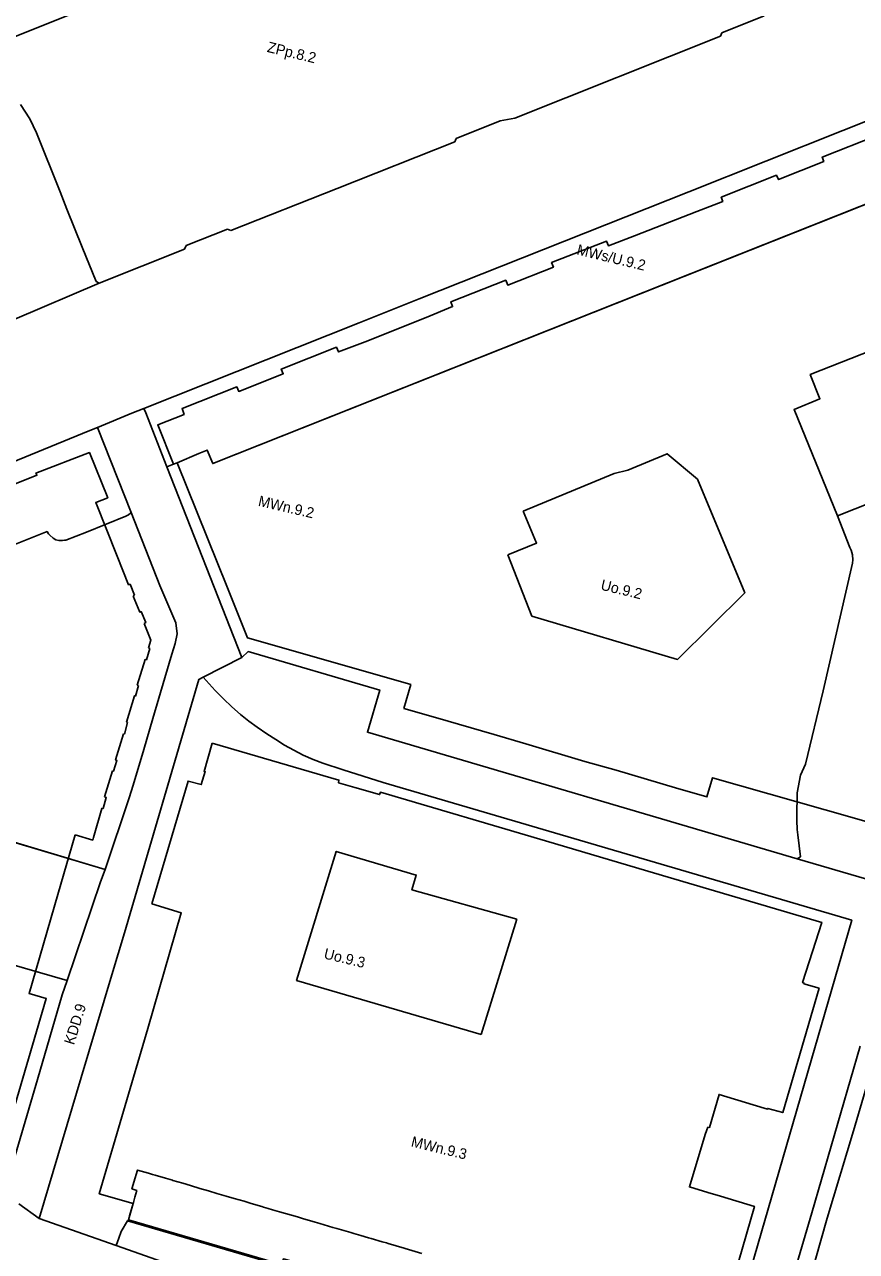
# Model space of a CAD drawing. Extents: x 7429686 to 7432896, y 5547954 to 5550600.
# Drawn here: x 7431433.9 to 7431748.3, y 5548706.1 to 5549169.6 of the extents above; entities that cross this region are included whole.
import ezdxf

# ---------------------------------------------------------------- set-up
doc = ezdxf.new("R2010")
doc.units = 0
for name, color, linetype in [('linie rozgraniczające', 7, 'Continuous'), ('obowiązująca linia zabudowy', 7, 'Continuous'), ('oznaczenia przeznaczeń', 7, 'Continuous')]:
    doc.layers.add(name, color=color, linetype=linetype)

msp = doc.modelspace()

# ---------------------------------------------------------------- linework, layer by layer
at = {"layer": 'linie rozgraniczające'}
for p, q in [((7431785.66, 5549115.2), (7431504.99, 5549003.74)), ((7431724.7, 5549024.21), (7431734.44, 5549028.21)), ((7431741.14, 5548983.95), (7431724.7, 5549024.21)), ((7431502.92, 5549008.85), (7431499.75, 5549007.52)), ((7431504.99, 5549003.74), (7431502.92, 5549008.85)), ((7431487.65, 5549002.56), (7431515.97, 5548930.47)), ((7431474.14, 5548985.19), (7431473.9, 5548984.95)), ((7431627.4, 5548973.7), (7431622.25, 5548985.72)), ((7431616.56, 5548969.31), (7431627.4, 5548973.7)), ((7431489.56, 5548931.69), (7431490.75, 5548935.82)), ((7431486.92, 5548922.77), (7431489.56, 5548931.69)), ((7431515.97, 5548930.47), (7431518.44, 5548932.69)), ((7431482.34, 5548907.49), (7431486.92, 5548922.77)), ((7431503.63, 5548920.58), (7431501.41, 5548923.1)), ((7431512.23, 5548911.8), (7431509.04, 5548914.81)), ((7431478.91, 5548895.76), (7431482.34, 5548907.49)), ((7431528.82, 5548899.44), (7431525.48, 5548901.64)), ((7431532.17, 5548897.4), (7431528.82, 5548899.44)), ((7431474.89, 5548882.25), (7431478.91, 5548895.76)), ((7431473.46, 5548877.47), (7431474.89, 5548882.25)), ((7431725.8, 5548877.54), (7431725.87, 5548879.36)), ((7431464.36, 5548850.33), (7431473.46, 5548877.47)), ((7431411.82, 5548866.07), (7431464.36, 5548850.33)), ((7431725.87, 5548854.38), (7431727.1, 5548855.2)), ((7431606.38, 5548788.03), (7431619.85, 5548831.65)), ((7431619.85, 5548831.65), (7431606.38, 5548788.03)), ((7431449.93, 5548808.45), (7431398.8, 5548823.21)), ((7431448.1, 5548803.02), (7431449.93, 5548808.45)), ((7431475.17, 5548732.25), (7431476.53, 5548736.85)), ((7431476.53, 5548736.85), (7431480.69, 5548735.63)), ((7431474.54, 5548730.08), (7431475.17, 5548732.25)), ((7431480.69, 5548735.63), (7431482.22, 5548735.18)), ((7431487.16, 5548733.74), (7431489.74, 5548732.98)), ((7431489.74, 5548732.98), (7431489.9, 5548732.93)), ((7431489.9, 5548732.93), (7431493.63, 5548731.84)), ((7431493.63, 5548731.84), (7431496.63, 5548730.96)), ((7431474.46, 5548729.81), (7431474.54, 5548730.08)), ((7431476.26, 5548729.09), (7431474.46, 5548729.81)), ((7431475.06, 5548724.64), (7431475.6, 5548726.65)), ((7431475.6, 5548726.65), (7431476.26, 5548729.09)), ((7431496.63, 5548730.96), (7431500.1, 5548729.94)), ((7431500.1, 5548729.94), (7431503.35, 5548728.99)), ((7431510.07, 5548727.02), (7431513.04, 5548726.15)), ((7431473.53, 5548719.51), (7431474.94, 5548724.18)), ((7431474.94, 5548724.18), (7431475.06, 5548724.64)), ((7431513.04, 5548726.15), (7431516.81, 5548725.05)), ((7431516.81, 5548725.05), (7431519.52, 5548724.26)), ((7431519.52, 5548724.26), (7431523.52, 5548723.08)), ((7431523.52, 5548723.08), (7431524.18, 5548722.89)), ((7431524.18, 5548722.89), (7431525.99, 5548722.36)), ((7431525.99, 5548722.36), (7431527.63, 5548721.88)), ((7431527.63, 5548721.88), (7431530.25, 5548721.12)), ((7431439.45, 5548718.51), (7431468.45, 5548708.34)), ((7431470.33, 5548713.59), (7431472.83, 5548717.66)), ((7431472.83, 5548717.66), (7431473.1, 5548718.1)), ((7431473.1, 5548718.1), (7431473.53, 5548719.51)), ((7431530.25, 5548721.12), (7431532.46, 5548720.47)), ((7431537.79, 5548718.9), (7431538.93, 5548718.57)), ((7431538.93, 5548718.57), (7431543.7, 5548717.17)), ((7431543.7, 5548717.17), (7431545.4, 5548716.68)), ((7431551.87, 5548714.78), (7431557.15, 5548713.23)), ((7431561.01, 5548712.1), (7431563.87, 5548711.27)), ((7431563.87, 5548711.27), (7431564.82, 5548710.99)), ((7431564.82, 5548710.99), (7431569.03, 5548709.75)), ((7431569.03, 5548709.75), (7431570.6, 5548709.3)), ((7431570.6, 5548709.3), (7431571.29, 5548709.09)), ((7431571.29, 5548709.09), (7431577.32, 5548707.33)), ((7431577.32, 5548707.33), (7431577.76, 5548707.2)), ((7431577.76, 5548707.2), (7431584.04, 5548705.36))]:
    msp.add_line(p, q, dxfattribs=at)
for points in [[(7431418.23, 5549160.27), (7431452.13, 5549173.77)], [(7431713.37, 5549172.84), (7431697.41, 5549166.43)], [(7431696.87, 5549165.14), (7431619.13, 5549134.23)], [(7431697.41, 5549166.43), (7431696.87, 5549165.14)], [(7431435.89, 5549133.99), (7431432.34, 5549139.33)], [(7431684.85, 5549106.33), (7431772.2, 5549141.08)], [(7431438.37, 5549128.66), (7431435.89, 5549133.99)], [(7431613.58, 5549133.25), (7431597.01, 5549126.59)], [(7431619.13, 5549134.23), (7431613.58, 5549133.25)], [(7431447.31, 5549106.39), (7431438.37, 5549128.66)], [(7431596.48, 5549125.24), (7431552, 5549107.62)], [(7431597.01, 5549126.59), (7431596.48, 5549125.24)], [(7431487.65, 5549002.56), (7431490.16, 5549003.53), (7431491.56, 5549004.06), (7431499.75, 5549007.52), (7431502.92, 5549008.85), (7431504.99, 5549003.74), (7431785.66, 5549115.2)], [(7431552, 5549107.62), (7431511.87, 5549091.76)], [(7431449.91, 5549099.9), (7431447.31, 5549106.39)], [(7431582.95, 5549065.95), (7431684.85, 5549106.33)], [(7431455.71, 5549085.44), (7431449.91, 5549099.9)], [(7431510.54, 5549092.31), (7431494.96, 5549086.12)], [(7431511.87, 5549091.76), (7431510.54, 5549092.31)], [(7431460.92, 5549072.46), (7431455.71, 5549085.44)], [(7431494.37, 5549084.78), (7431462.06, 5549071.92)], [(7431494.96, 5549086.12), (7431494.37, 5549084.78)], [(7431430.25, 5549058.28), (7431462.06, 5549071.92)], [(7431462.06, 5549071.92), (7431460.92, 5549072.46)], [(7431560.27, 5549056.88), (7431582.95, 5549065.95)], [(7431479.01, 5549024.58), (7431560.27, 5549056.88)], [(7431798.27, 5549018.65), (7431791.38, 5549035.58), (7431789.74, 5549039.66), (7431778.26, 5549035.05), (7431777.18, 5549034.62), (7431769.87, 5549052.73), (7431730.81, 5549037.32), (7431734.44, 5549028.21), (7431724.7, 5549024.21), (7431741.14, 5548983.95)], [(7431734.44, 5549028.21), (7431730.81, 5549037.32), (7431769.87, 5549052.73), (7431777.18, 5549034.62), (7431778.26, 5549035.05)], [(7431474.47, 5549022.72), (7431479.01, 5549024.58)], [(7431479.65, 5549022.93), (7431479.01, 5549024.58)], [(7431461.42, 5549017.39), (7431474.47, 5549022.72)], [(7431487.65, 5549002.56), (7431479.65, 5549022.93)], [(7431458.52, 5549016.21), (7431381.36, 5548984.68)], [(7431461.42, 5549017.39), (7431458.52, 5549016.21)], [(7431474.14, 5548985.19), (7431461.42, 5549017.39)], [(7431499.75, 5549007.52), (7431491.56, 5549004.06), (7431490.16, 5549003.53), (7431487.65, 5549002.56)], [(7431616.56, 5548969.31), (7431625.6, 5548946.1), (7431680.64, 5548929.72), (7431706.02, 5548954.88), (7431688.21, 5548997.84), (7431676.68, 5549007.45), (7431661.81, 5549001.29), (7431656.64, 5548999.97), (7431622.25, 5548985.72)], [(7431622.25, 5548985.72), (7431656.64, 5548999.97), (7431661.81, 5549001.29), (7431676.68, 5549007.45), (7431688.21, 5548997.84)], [(7431741.14, 5548983.95), (7431802.38, 5549008.24)], [(7431515.97, 5548930.47), (7431487.65, 5549002.56)], [(7431688.21, 5548997.84), (7431706.02, 5548954.88), (7431680.64, 5548929.72), (7431625.6, 5548946.1), (7431616.56, 5548969.31)], [(7431425.44, 5548971.3), (7431442.42, 5548978.05), (7431442.93, 5548977.2), (7431443.45, 5548976.63), (7431444.69, 5548975.54), (7431445.74, 5548974.96), (7431446.79, 5548974.7), (7431447.58, 5548974.62), (7431448.24, 5548974.62), (7431449.01, 5548974.74), (7431449.47, 5548974.86), (7431457.29, 5548977.87), (7431472.2, 5548983.89), (7431473.17, 5548984.4), (7431473.9, 5548984.95), (7431474.14, 5548985.19)], [(7431473.9, 5548984.95), (7431473.17, 5548984.4), (7431472.2, 5548983.89), (7431457.29, 5548977.87), (7431449.47, 5548974.86), (7431449.01, 5548974.74), (7431448.24, 5548974.62), (7431447.58, 5548974.62), (7431446.79, 5548974.7), (7431445.74, 5548974.96), (7431444.69, 5548975.54), (7431443.45, 5548976.63), (7431442.93, 5548977.2), (7431442.42, 5548978.05)], [(7431474.14, 5548985.19), (7431485.04, 5548957.62), (7431491, 5548943.55), (7431491.6, 5548939.41), (7431490.75, 5548935.82), (7431489.56, 5548931.69), (7431486.92, 5548922.77), (7431482.34, 5548907.49), (7431478.91, 5548895.76), (7431474.89, 5548882.25), (7431473.46, 5548877.47), (7431464.36, 5548850.33)], [(7431491, 5548943.55), (7431485.04, 5548957.62), (7431474.14, 5548985.19)], [(7431622.25, 5548985.72), (7431627.4, 5548973.7), (7431616.56, 5548969.31)], [(7431741.14, 5548983.95), (7431745.78, 5548971.99), (7431746.27, 5548971.03), (7431746.77, 5548969.28), (7431746.85, 5548967.38), (7431746.71, 5548966.07), (7431735.66, 5548917.92), (7431729, 5548890.15), (7431727.13, 5548886.07), (7431725.87, 5548879.36), (7431725.8, 5548877.54), (7431725.78, 5548872.17), (7431725.77, 5548868.88), (7431725.89, 5548865.49), (7431726.11, 5548863.45), (7431727.1, 5548855.2), (7431725.87, 5548854.38)], [(7431729, 5548890.15), (7431735.66, 5548917.92), (7431746.71, 5548966.07), (7431746.85, 5548967.38), (7431746.77, 5548969.28), (7431746.27, 5548971.03), (7431745.78, 5548971.99), (7431741.14, 5548983.95)], [(7431442.42, 5548978.05), (7431425.44, 5548971.3), (7431214.81, 5548887.54)], [(7431490.75, 5548935.82), (7431491.6, 5548939.41), (7431491, 5548943.55)], [(7431501.41, 5548923.1), (7431515.97, 5548930.47)], [(7431725.87, 5548854.38), (7431563.43, 5548902.25), (7431568.12, 5548918.15), (7431518.44, 5548932.69), (7431515.97, 5548930.47)], [(7431518.44, 5548932.69), (7431568.12, 5548918.15), (7431563.43, 5548902.25), (7431725.87, 5548854.38)], [(7431501.41, 5548923.1), (7431499.78, 5548922.18), (7431471.6, 5548826.52), (7431466.86, 5548810.61), (7431455.3, 5548771.76), (7431439.45, 5548718.51)], [(7431439.45, 5548718.51), (7431455.3, 5548771.76), (7431466.86, 5548810.61), (7431471.6, 5548826.52), (7431499.78, 5548922.18), (7431501.41, 5548923.1)], [(7431501.41, 5548923.1), (7431503.63, 5548920.58)], [(7431509.04, 5548914.81), (7431505.97, 5548918), (7431503.63, 5548920.58)], [(7431503.63, 5548920.58), (7431505.97, 5548918), (7431509.04, 5548914.81), (7431512.23, 5548911.8), (7431515.52, 5548908.91), (7431518.64, 5548906.47), (7431521.8, 5548904.16), (7431525.48, 5548901.64), (7431528.82, 5548899.44), (7431532.17, 5548897.4), (7431535.64, 5548895.42), (7431539.13, 5548893.58), (7431542.89, 5548892), (7431546.65, 5548890.61), (7431554.28, 5548888.03), (7431569.39, 5548883.24), (7431746.47, 5548831.23), (7431732.49, 5548783.01), (7431694.68, 5548652.52)], [(7431518.64, 5548906.47), (7431515.52, 5548908.91), (7431512.23, 5548911.8)], [(7431525.48, 5548901.64), (7431521.8, 5548904.16), (7431518.64, 5548906.47)], [(7431539.13, 5548893.58), (7431535.64, 5548895.42), (7431532.17, 5548897.4)], [(7431746.47, 5548831.23), (7431569.39, 5548883.24), (7431554.28, 5548888.03), (7431546.65, 5548890.61), (7431542.89, 5548892), (7431539.13, 5548893.58)], [(7431725.87, 5548879.36), (7431727.13, 5548886.07), (7431729, 5548890.15)], [(7431725.89, 5548865.49), (7431725.77, 5548868.88), (7431725.78, 5548872.17), (7431725.8, 5548877.54)], [(7431411.42, 5548866.34), (7431385.82, 5548873.99), (7431383.14, 5548872.81), (7431369.44, 5548832.95), (7431371.28, 5548830.24), (7431395.15, 5548823.28), (7431396.28, 5548822.97), (7431398.8, 5548823.21), (7431449.93, 5548808.45)], [(7431464.36, 5548850.33), (7431411.82, 5548866.07), (7431411.42, 5548866.34)], [(7431727.1, 5548855.2), (7431726.11, 5548863.45), (7431725.89, 5548865.49)], [(7431619.85, 5548831.65), (7431580.24, 5548842.77), (7431581.89, 5548848.26), (7431551.65, 5548857.24), (7431536.68, 5548808.47), (7431606.38, 5548788.03)], [(7431606.38, 5548788.03), (7431536.68, 5548808.47), (7431551.65, 5548857.24), (7431581.89, 5548848.26), (7431580.24, 5548842.77), (7431619.85, 5548831.65)], [(7431834.22, 5548822.81), (7431725.87, 5548854.38)], [(7431462.54, 5548845.71), (7431464.36, 5548850.33)], [(7431449.93, 5548808.45), (7431462.54, 5548845.71)], [(7431694.68, 5548652.52), (7431732.49, 5548783.01), (7431746.47, 5548831.23)], [(7431449.93, 5548808.45), (7431448.1, 5548803.02), (7431438.75, 5548771.09), (7431425.69, 5548726.51)], [(7431425.69, 5548726.51), (7431438.75, 5548771.09), (7431448.1, 5548803.02)], [(7431731.33, 5548720.67), (7431749.67, 5548783.7)], [(7431584.04, 5548705.36), (7431577.76, 5548707.2), (7431577.32, 5548707.33), (7431571.29, 5548709.09), (7431570.6, 5548709.3), (7431569.03, 5548709.75), (7431564.82, 5548710.99), (7431563.87, 5548711.27), (7431561.01, 5548712.1), (7431558.35, 5548712.88), (7431557.15, 5548713.23), (7431551.87, 5548714.78), (7431550.42, 5548715.2), (7431545.4, 5548716.68), (7431543.7, 5548717.17), (7431538.93, 5548718.57), (7431537.79, 5548718.9), (7431536.97, 5548719.14), (7431532.46, 5548720.47), (7431530.25, 5548721.12), (7431527.63, 5548721.88), (7431525.99, 5548722.36), (7431524.18, 5548722.89), (7431523.52, 5548723.08), (7431519.52, 5548724.26), (7431516.81, 5548725.05), (7431513.04, 5548726.15), (7431510.07, 5548727.02), (7431506.57, 5548728.05), (7431503.35, 5548728.99), (7431500.1, 5548729.94), (7431496.63, 5548730.96), (7431493.63, 5548731.84), (7431489.9, 5548732.93), (7431489.74, 5548732.98), (7431487.16, 5548733.74), (7431483.18, 5548734.9), (7431482.22, 5548735.18), (7431480.69, 5548735.63), (7431476.53, 5548736.85), (7431475.17, 5548732.25), (7431474.54, 5548730.08), (7431474.46, 5548729.81), (7431476.26, 5548729.09), (7431475.6, 5548726.65), (7431475.06, 5548724.64), (7431474.94, 5548724.18), (7431473.53, 5548719.51), (7431473.1, 5548718.1)], [(7431482.22, 5548735.18), (7431483.18, 5548734.9), (7431487.16, 5548733.74)], [(7431503.35, 5548728.99), (7431506.57, 5548728.05), (7431510.07, 5548727.02)], [(7431439.45, 5548718.51), (7431431.66, 5548724.14)], [(7431468.45, 5548708.34), (7431439.45, 5548718.51)], [(7431472.83, 5548717.66), (7431470.33, 5548713.59), (7431469.46, 5548711.15), (7431468.45, 5548708.34)], [(7431473.1, 5548718.1), (7431472.83, 5548717.66)], [(7431531.3, 5548700.57), (7431472.83, 5548717.66)], [(7431532.46, 5548720.47), (7431536.97, 5548719.14), (7431537.79, 5548718.9)], [(7431710.91, 5548650.94), (7431731.33, 5548720.67)], [(7431468.45, 5548708.34), (7431469.46, 5548711.15), (7431470.33, 5548713.59)], [(7431545.4, 5548716.68), (7431550.42, 5548715.2), (7431551.87, 5548714.78)], [(7431557.15, 5548713.23), (7431558.35, 5548712.88), (7431561.01, 5548712.1)], [(7431496.71, 5548698.43), (7431468.45, 5548708.34)]]:
    msp.add_lwpolyline(points, dxfattribs=at)
at = {"layer": 'obowiązująca linia zabudowy'}
for p, q in [((7431474.96, 5548953.68), (7431475.38, 5548954)), ((7431471.64, 5548901.52), (7431472.82, 5548905.93)), ((7431472.82, 5548905.93), (7431472.45, 5548906.08)), ((7431471.28, 5548901.67), (7431471.64, 5548901.52)), ((7431464.14, 5548877.81), (7431467.1, 5548887.65))]:
    msp.add_line(p, q, dxfattribs=at)
for points in [[(7431756.29, 5549127.83), (7431735.31, 5549119.54), (7431735.9, 5549117.87), (7431718.83, 5549111.02), (7431718.01, 5549112.67), (7431697.13, 5549104.32), (7431697.75, 5549102.78), (7431687.9, 5549098.92), (7431664.36, 5549089.76), (7431654.49, 5549086.02), (7431653.75, 5549087.77), (7431633.02, 5549079.69), (7431633.72, 5549077.94), (7431616.48, 5549071.15), (7431615.69, 5549072.98), (7431594.97, 5549064.88), (7431595.62, 5549063.01), (7431585.61, 5549058.97), (7431562.6, 5549049.76), (7431552.54, 5549045.92), (7431551.73, 5549047.7), (7431530.89, 5549039.41), (7431531.61, 5549037.64), (7431514.85, 5549030.97), (7431514.15, 5549032.69), (7431493.38, 5549024.49), (7431494.18, 5549022.33), (7431484.24, 5549018.41), (7431490.16, 5549003.53)], [(7431475.38, 5548954), (7431473.76, 5548958.14), (7431473.19, 5548957.94), (7431468.89, 5548968.7), (7431460.76, 5548988.97), (7431465.29, 5548990.8), (7431458.36, 5549007.86), (7431438.2, 5549000.13), (7431438.56, 5548999.31), (7431400.27, 5548984.05)], [(7431490.16, 5549003.53), (7431491.56, 5549004.06), (7431510.53, 5548956.83), (7431518.13, 5548937.88), (7431564.44, 5548924.63), (7431579.84, 5548920.22), (7431577.21, 5548911.2)], [(7431479.12, 5548943.33), (7431479.65, 5548943.64), (7431477.91, 5548947.81), (7431477.41, 5548947.65), (7431474.96, 5548953.68)], [(7431475.38, 5548954), (7431475.38, 5548954)], [(7431480.69, 5548934.08), (7431481.65, 5548937), (7431479.12, 5548943.33)], [(7431479.98, 5548929.64), (7431481.17, 5548933.88), (7431480.69, 5548934.08)], [(7431476.97, 5548919.84), (7431476.49, 5548920.07), (7431479.47, 5548929.77), (7431479.98, 5548929.64)], [(7431472.45, 5548906.08), (7431475.43, 5548916.02), (7431475.77, 5548915.91), (7431476.97, 5548919.84)], [(7431577.21, 5548911.2), (7431589.18, 5548907.8), (7431611.32, 5548901.4), (7431623.3, 5548897.83), (7431645.57, 5548891.16), (7431657.48, 5548887.86), (7431679.82, 5548881.19), (7431691.72, 5548877.82), (7431693.9, 5548885.03), (7431746.6, 5548869.97), (7431849.61, 5548840.54), (7431847.29, 5548831.84)], [(7431467.1, 5548887.65), (7431467.54, 5548887.56), (7431468.76, 5548891.55), (7431468.27, 5548891.76), (7431471.28, 5548901.67)], [(7431504.72, 5548898.16), (7431501.7, 5548887.47), (7431502.19, 5548887.38), (7431500.63, 5548882.46), (7431495.67, 5548883.79), (7431482, 5548837.43)], [(7431734.2, 5548805.59), (7431728.37, 5548807.22), (7431728.47, 5548807.49), (7431727.89, 5548807.65), (7431731.65, 5548819.4), (7431735.16, 5548830.39), (7431669.46, 5548849.77), (7431630.77, 5548861.25), (7431568.34, 5548879.6), (7431568.03, 5548878.71), (7431558.66, 5548881.41), (7431552.52, 5548883.18), (7431552.65, 5548884.19), (7431504.72, 5548898.16)], [(7431463.62, 5548873.38), (7431464.77, 5548877.57), (7431464.14, 5548877.81)], [(7431452.94, 5548863.46), (7431459.65, 5548861.52), (7431459.93, 5548862.49), (7431463.05, 5548873.47), (7431463.62, 5548873.38)], [(7431421.06, 5548733.02), (7431421.72, 5548734.55), (7431421.34, 5548734.64), (7431424.56, 5548743.62), (7431424.97, 5548743.51), (7431425.58, 5548745.28), (7431424.32, 5548745.67), (7431427.16, 5548754.1), (7431428.03, 5548753.92), (7431442.08, 5548801.7), (7431435.57, 5548803.59), (7431446.4, 5548840.91), (7431452.94, 5548863.46)], [(7431482, 5548837.43), (7431493.08, 5548834.02), (7431480.5, 5548790.37), (7431462.08, 5548727.93), (7431474.94, 5548724.18)], [(7431773.26, 5548819.35), (7431770.21, 5548808.72), (7431766.52, 5548795.89), (7431760.63, 5548797.5), (7431747.1, 5548751.63), (7431737.24, 5548718.65), (7431724.14, 5548672.46)], [(7431677.77, 5548664.65), (7431691.6, 5548660.41), (7431709.71, 5548723.13), (7431696.9, 5548726.97), (7431692.03, 5548728.43), (7431685.12, 5548730.5), (7431691.1, 5548750.31), (7431692.09, 5548753.03), (7431692.74, 5548752.98), (7431696.32, 5548765.42), (7431709.17, 5548761.44), (7431714.67, 5548759.88), (7431714.76, 5548760.15), (7431720.43, 5548758.57), (7431734.2, 5548805.59)], [(7431474.94, 5548724.18), (7431473.1, 5548718.1), (7431530.98, 5548701.18), (7431531.71, 5548703.27), (7431546.32, 5548699.1), (7431545.58, 5548696.69), (7431556.57, 5548693.43), (7431561.2, 5548692.02), (7431572.04, 5548688.79), (7431581.68, 5548686.02), (7431587.86, 5548684.18), (7431592.51, 5548682.76), (7431603.39, 5548679.59), (7431604.13, 5548681.81), (7431612.8, 5548679.43), (7431618.58, 5548677.53), (7431618.01, 5548675.55), (7431675.86, 5548658.53)]]:
    msp.add_lwpolyline(points, dxfattribs=at)

# ---------------------------------------------------------------- texts
at = {"layer": 'oznaczenia przeznaczeń'}
for s, rotation, p in [('ZPp.8.2', 346.4891, (7431525.28, 5549159.29)), ('MWs/U.9.2', 346.4891, (7431642.3, 5549082.75)), ('MWn.9.2', 347.0609, (7431521.91, 5548987.8)), ('Uo.9.2', 346.4891, (7431651.34, 5548956.12)), ('Uo.9.3', 346.4891, (7431546.72, 5548816.83)), ('KDD.9', 72.7589, (7431452.54, 5548783.88)), ('MWn.9.3', 346.4891, (7431579.67, 5548745.79))]:
    msp.add_text(s, height=4, rotation=rotation, dxfattribs=at).set_placement(p)

doc.saveas('drawing.dxf')
